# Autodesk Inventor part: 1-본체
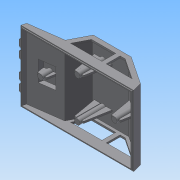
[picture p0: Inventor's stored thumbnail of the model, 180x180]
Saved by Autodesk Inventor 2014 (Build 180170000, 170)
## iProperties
Created: 2015-05
Part Number: 1-본체
Material: 일반
Document SubType Name: Modeling
Designer: Administrator
Density: 1 g/cm^3
Appearance: 기본값
Author: Administrator
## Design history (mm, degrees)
sketch "스케치1"
  geometry: L1 (-61, 0)-(61, 0); L2 (-61, 0)-(-59.66, 5); L3 (-12.679, 30)-(28.321, 30); L4 (28.321, 30)-(58.321, 10); L5 (58.321, 10)-(61, 0); L6 (-59.66, 5)-(-22.975, 10); L7 (-22.975, 10)-(-12.679, 30); 2 further points
  constraints: 14 end point, 1 coincident, 1 horizontal, 1 midpoint, 1 parallel
  dimensions: "d1" = 122 distance of L1.start L1.end; "d13" = 30 vertical distance of L1.end L3.end; "d14" = 105 deg angle of L1 L5; "d15" = 30 horizontal distance of L4.end L3.end; "d16" = 20 vertical distance of L4.end L3.end; "d17" = 41 distance of L3.start L3.end; "d27" = 5 vertical distance of L2.end L1.start; "d28" = 105 deg angle of L1 L2; "d30" = 125 deg angle of L7 L6; "d31" = 20 vertical distance of L3.start L6.end
extrude "돌출1" new body sketch "스케치1" distance "d18" = 76; taper "d19" = 0 deg
node "작업 평면1"
sketch "스케치5"
  geometry: L1 (-22.975, 10)-(-59.66, 5) reference; L2 (-31.423, 13.895)-(-47.633, 11.685); L3 (-31.423, 13.895)-(-28.944, 9.186); L4 (-47.633, 11.685)-(-48.761, 6.486); L5 (-59.66, 5)-(-61, 0) reference; 1 further point
  constraints: 6 end point, 2 point on line, 1 parallel
  dimensions: "d51" = 70 deg angle of L1 L3; "d52" = 70 deg angle of L1 L4; "d53" = 20 distance of L3.end L4.end; "d55" = 11 distance of L1.end L4.end; "d56" = 5 distance between parallel lines of L1 L2
extrude "돌출3" join sketch "스케치5" stored distance "d57" = 26; taper "d58" = 0 deg
feature "쉘2" dims "d62" = 2
sketch "스케치6"
  geometry: L1 (41, 0)-(41, -76) reference; L2 (73.679, 0)-(73.679, -76) reference; 3 further points
  constraints: 1 horizontal alignment, 1 midpoint, 1 other
  dimensions: "d59" = 50 distance from line of L2 point (23.679, -38)
feature "엠보싱1" sketch "스케치6" dims "d1" = 122, "d13" = 30, "d14" = 105 deg, "d15" = 30, "d16" = 20, "d17" = 41, "d27" = 5, "d28" = 105 deg, "d30" = 125 deg, "d31" = 20, "d32" = 15, "d34" = 34, "d36" = 5, "d37" = 5, "d38" = 28, "d39" = 5, "d60" = 0.5, "d61" = 0
sketch "스케치3"
  geometry: L1 (58.321, 10)-(28.321, 30) reference; L2 (28.321, 30)-(-12.679, 30) reference; L3 (-12.679, 30)-(-22.975, 10) reference; L4 (-9.63, 25)-(16.648, 25); L5 (16.648, 25)-(16.648, 10); L6 (16.648, 10)-(-17.352, 10); L7 (-17.352, 10)-(-9.63, 25); L8 (21.307, 25)-(21.307, 10); L9 (21.307, 10)-(49.307, 10); L10 (49.307, 10)-(26.807, 25); L11 (26.807, 25)-(21.307, 25); 1 further point
  constraints: 16 end point, 5 parallel, 3 perpendicular, 1 collinear, 1 point on line
  dimensions: "d32" = 15 vertical distance of L6.end L4.start; "d34" = 34 distance of L5.end L6.end; "d36" = 5 distance between parallel lines of L3 L7; "d37" = 5 distance between parallel lines of L4 L2; "d38" = 28 distance of L8.end L9.end; "d39" = 5 distance between parallel lines of L10 L1
extrude "돌출2" cut sketch "스케치3" stored distance "d40" = 76; taper "d41" = 0 deg
sketch "스케치7"
  geometry: L1 (119.929, 74)-(119.929, 2) reference; L2 (122, 0)-(122, 76) reference; C1 r 3 at (101, 38); C2 r 3 at (61, 60); C3 r 3 at (61, 16); C4 r 3 at (21, 38); 2 further points
  constraints: 4 centre point, 2 equal radius, 2 horizontal alignment, 1 midpoint, 1 vertical alignment
  dimensions: "d63" = 21 distance from line of L2 C1.centre; "d64" = 40 horizontal distance of C3.centre C1.centre; "d65" = 6 diameter of C1; "d66" = 6 diameter of C2; "d67" = 40 horizontal distance of C4.centre C3.centre; "d68" = 22 vertical distance of C3.centre C1.centre; "d69" = 22 vertical distance of C2.centre C1.centre
extrude "돌출4" join sketch "스케치7" stored distance "d70" = 10; taper "d71" = 0 deg
node "작업 평면2"
sketch "스케치8"
  geometry: L1 (-61, 0)-(61, 0) reference; L2 (43, 0)-(43, 17.81) reference; L3 (37, 0)-(37, 21.81) reference; L4 (-37, 0)-(-37, 11.116) reference; L5 (49.307, 10)-(21.307, 10) reference; L6 (21.307, 10)-(21.307, 25) reference; L7 (21.307, 25)-(26.807, 25) reference; L8 (26.807, 25)-(49.307, 10) reference; L9 (-17.352, 10)-(-9.63, 25) reference; L10 (-9.63, 25)-(16.648, 25) reference; L11 (16.648, 25)-(16.648, 10) reference; L12 (16.648, 10)-(-17.352, 10) reference; L13 (-61, 0)-(61, 0) reference; L14 (61, 0)-(58.321, 10) reference; L15 (58.321, 10)-(28.321, 30) reference; L16 (28.321, 30)-(-12.679, 30) reference; L17 (-12.679, 30)-(-22.975, 10) reference; L18 (-59.66, 5)-(-61, 0) reference; L19 (-43, 0)-(-43, 10.298) reference; L20 (43, 2)-(45, 2); L21 (45, 2)-(47.663, 17.105); L22 (37, 2)-(35, 2); L23 (35, 2)-(30.295, 28.684); L24 (-37, 2)-(-35, 2); L25 (-35, 2)-(-33.304, 11.62); L26 (-43, 2)-(-45, 2); L27 (-45, 2)-(-46.205, 8.834); L28 (-32.54, 11.724)-(-45.975, 9.893) reference; L29 (-30.062, 7.016)-(-32.54, 11.724) reference; L30 (-45.975, 9.893)-(-47.103, 4.693) reference; L31 (56.584, 8.754)-(27.715, 28) reference; 5 further points; 3 other entities
  constraints: 16 end point, 12 point on line, 6 collinear, 2 perpendicular, 1 parallel, 7 other
  dimensions: "d74" = 10 distance of L20.end L22.end; "d75" = 2 distance between parallel lines of L1 L20; "d76" = 10 deg angle of L2 L21; "d77" = 10 deg angle of L3 L23; "d78" = 10 distance of L24.end L26.end; "d79" = 2 distance between parallel lines of L1 L24; "d80" = 10 deg angle of L27 L19
extrude "돌출6" join sketch "스케치8" stored distance "d83" = 2; taper "d84" = 0 deg
node "작업 평면3"
sketch "스케치9"
  geometry: L1 (27.715, 28)-(-11.46, 28) reference; L2 (-61, 0)-(61, 0) reference; L3 (3, 0)-(3, 28) reference; L4 (-3, 0)-(-3, 28) reference; L5 (3, 2)-(5, 2); L6 (-3, 2)-(-5, 2); L7 (-5, 2)-(-9.585, 28); L8 (5, 2)-(9.585, 28); 1 further point
  constraints: 8 end point, 4 point on line, 2 collinear, 1 horizontal, 1 perpendicular
  dimensions: "d86" = 2 distance between parallel lines of L2 L5; "d87" = 10 deg angle of L3 L8; "d88" = 10 deg angle of L7 L4; "d89" = 10 distance of L6.end L5.end
extrude "돌출7" join sketch "스케치9" stored distance "d90" = 2; taper "d91" = 0 deg
node "작업 평면4"
sketch "스케치10"
  geometry: L1 (-9.585, 28)-(-5, 2) reference; L2 (5, 2)-(9.585, 28) reference; L3 (3, 2)-(5, 2) reference; L4 (-5, 2)-(-3, 2) reference; L5 (-3, 2)-(-3, 28) reference; L6 (3, 28)-(3, 2) reference; L7 (27.715, 28)-(-11.46, 28) reference; 1 further point
extrude "돌출8" join sketch "스케치10" distance "d93" = 2; taper "d94" = 0 deg
sketch "스케치11"
  geometry: L1 (119.929, 74)-(119.929, 2) reference; L2 (119.929, 2)-(2.071, 2) reference; L3 (2.071, 2)-(2.071, 74) reference; L4 (2.071, 74)-(119.929, 74) reference; L5 (0, 0)-(122, 0) reference; L6 (1.265, 75.037)-(120.929, 75.037); L7 (120.929, 75.037)-(120.929, 1); L8 (120.929, 1)-(1.265, 1); L9 (1.265, 1)-(1.265, 75.037); L10 (1.265, 75.037)-(120.929, 1); L11 (120.929, 75.037)-(1.265, 1); L12 (2.265, 74.037)-(119.929, 74.037); L13 (119.929, 74.037)-(119.929, 2); L14 (119.929, 2)-(2.265, 2); L15 (2.265, 2)-(2.265, 74.037); L16 (2.265, 74.037)-(119.929, 2); L17 (119.929, 74.037)-(2.265, 2); 2 further points
  constraints: 24 end point, 4 midpoint, 4 parallel, 2 horizontal, 2 perpendicular
  dimensions: "d95" = 1 distance between parallel lines of L1 L7; "d96" = 1 distance between parallel lines of L5 L8
extrude "돌출9" join sketch "스케치11" distance "d97" = 1; taper "d98" = 0 deg
node "작업 평면5"
sketch "스케치12"
  geometry: L1 (-10, 0)-(-10, 76) reference; L2 (-13.895, 51)-(-13.895, 25) reference; A1 r 4 centre (0, 17) between (0, 21) and (0, 13); A2 r 4 centre (0, 28) between (0, 32) and (0, 24); A3 r 4 centre (0, 48) between (0, 52) and (0, 44); A4 r 4 centre (0, 59) between (0, 63) and (0, 55); 3 further points
  constraints: 8 point on circle, 4 centre point, 3 equal radius, 1 midpoint, 13 other
  dimensions: "d100" = 20 distance of A3.centre A2.centre; "d101" = 10 vertical distance of point (-13.895, 38) A2.centre; "d102" = 11 distance of A4.centre A3.centre; "d103" = 11 distance of A1.centre A2.centre; "d104" = 8 diameter of A1
extrude "돌출10" join sketch "스케치12" stored distance "d105" = 1; taper "d106" = 0 deg
chamfer "모따기1" distance "d107" = 1; stored, may be unused: second distance "d108" = 2, angle "d109" = 45 deg
node "솔리드1"
node "투영된 루프1"
other parameters: "d72" = 38, "d85" = 22, "d92" = -22, "d99" = -63
